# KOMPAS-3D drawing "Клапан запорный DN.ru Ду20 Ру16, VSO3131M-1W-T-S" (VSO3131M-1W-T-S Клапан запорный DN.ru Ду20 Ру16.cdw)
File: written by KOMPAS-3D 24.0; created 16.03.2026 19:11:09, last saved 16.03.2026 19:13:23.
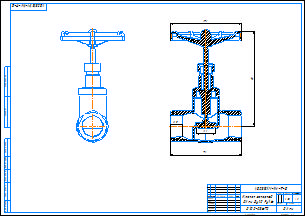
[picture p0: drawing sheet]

Document properties: c3d_UniqueCompID: 94d3474e-3e6e-4ddd-ad0b-ef51eb5e31da; Обозначение: VSO3131M-1W-T-S; Наименование: Клапан запорный DN.ru Ду20 Ру16; Материал: Сталь 10 ГОСТ 1050-2013; Автор: artiomk228874@gmail.com; Класс точности: c; Знак неуказанной шероховатости: Шероховатость не задана; Рассекать на разрезах: Да; Автор: artiomk228874@gmail.com; Форматы листов документа: A2; Полное имя файла: VSO3131M-1W-T-S Клапан запорный DN.ru Ду20 Ру16.m3d; Масса: 0.38; Наименование: Клапан запорный DN.ru Ду20 Ру16; Количество листов документа: 1; Примечание: D100-03670

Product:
- Body: Тело 1  | qty 1
    Масса: 0.280197
- Part/product: Клапан запорный DN.ru Ду20 Ру16  | designation VSO3131M-1W-T-S
    Масса: 0.38
    Раздел спецификации: Прочие изделия
    Форматы листов документа: A2
    Примечание: D100-03670
    additional columns: 94d3474e-3e6e-4ddd-ad0b-ef51eb5e31da; VSO3131M-1W-T-S; Сталь 10 ГОСТ 1050-2013; artiomk228874@gmail.com; c; Шероховатость не задана; Да

Views: Вид 1, Спереди
Referenced files in C:\Users\artio\OneDrive\Рабочий стол\Клапан запорный DN.ru VSO3131M-1W-T-S Ду15-Ду50 Ру16\Ду20\: VSO3131M-1W-T-S Клапан запорный DN.ru Ду20 Ру16.m3d, VSO3131M-1W-T-S Клапан запорный DN.ru Ду20 Ру16.cdw
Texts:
  VSO3131M-1W-T-S
  Клапан запорный
  DN.ru Ду20 Ру16
  Клапан запорный DN.ru Ду20 Ру16
  VSO3131M-1W-T-S Клапан запорный DN.ru Ду20 Ру16
Dimensions and other numbers on the sheet: 0; 3; 2; 4; 2:1; 1; 0,38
